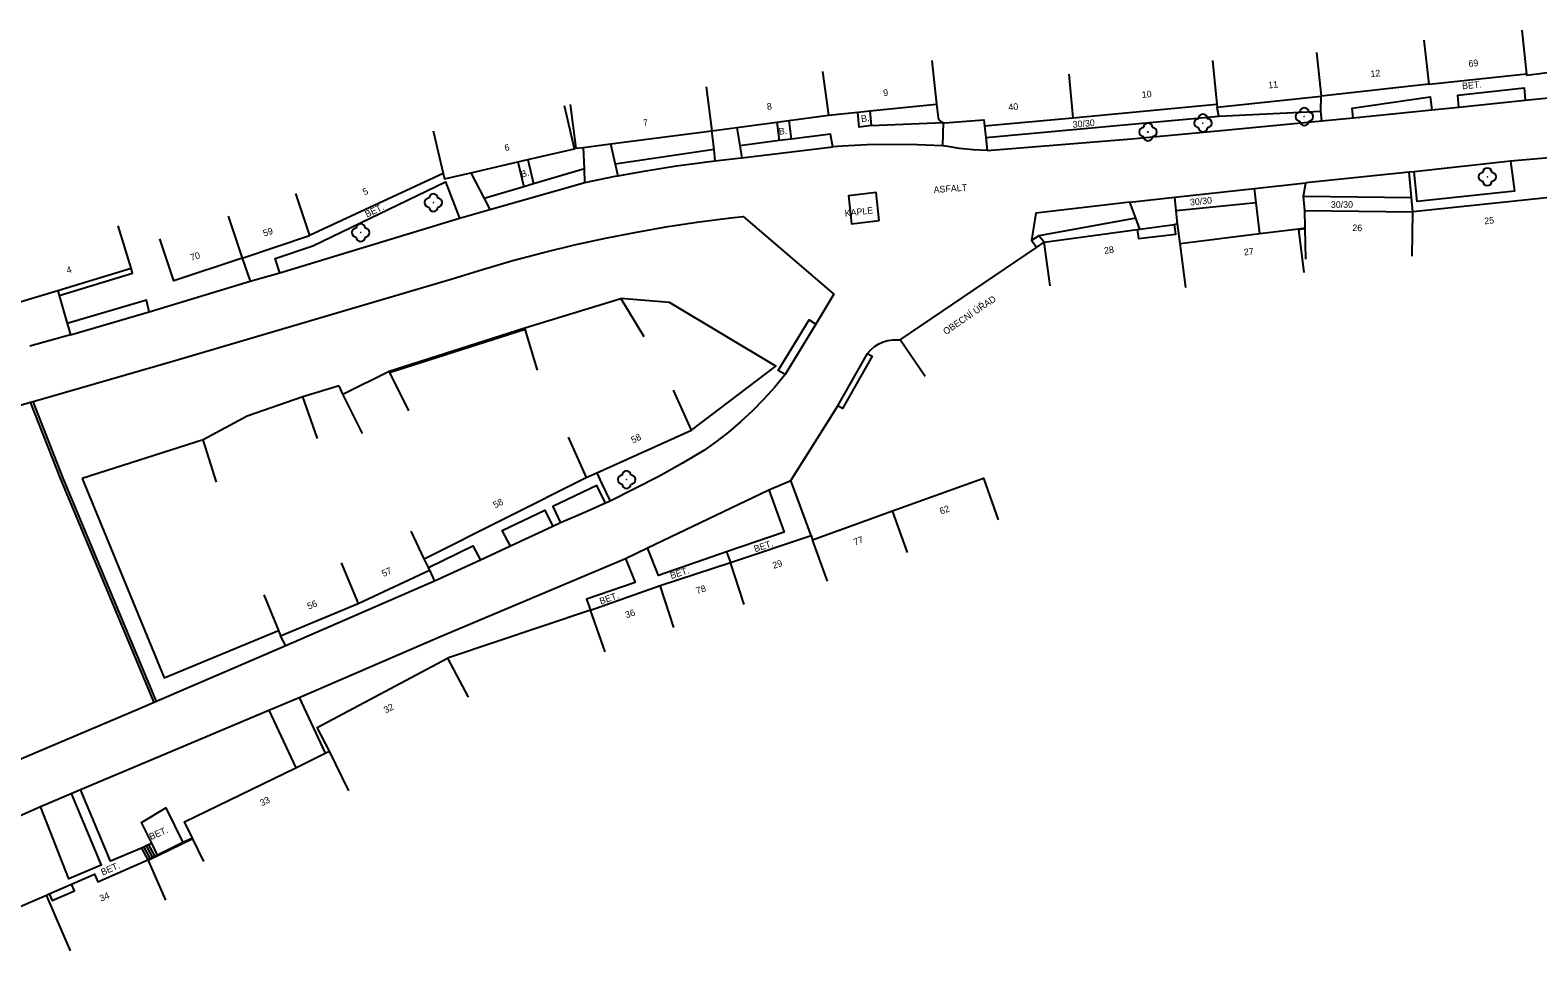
# Model space of a CAD drawing. Extents: x -544674 to -541478, y -1199076 to -1195527.
# Drawn here: x -544563.4 to -544392.6, y -1198429.7 to -1198325.4 of the extents above; entities that cross this region are included whole.
import ezdxf

# ---------------------------------------------------------------- set-up
doc = ezdxf.new("R2010")
doc.units = 0
for name, color, linetype in [('BUDOVY_MĚŘ', 7, 'Continuous'), ('POMOC_POPIS', 7, 'Continuous'), ('ROZHRANÍ_PLOCH', 7, 'Continuous'), ('ZELEŇ', 7, 'Continuous'), ('ZN_DOPLŇKOVÉ', 7, 'Continuous'), ('Č_POPIS_ORIENT', 7, 'Continuous')]:
    doc.layers.add(name, color=color, linetype=linetype)

msp = doc.modelspace()

# ---------------------------------------------------------------- linework, layer by layer
at = {"layer": 'BUDOVY_MĚŘ'}
for points in [[(-544394.36, -1198325.38), (-544393.83, -1198330.35)], [(-544417.64, -1198327.9), (-544417.11, -1198332.87)], [(-544405.46, -1198326.52), (-544404.9, -1198331.49)], [(-544461.21, -1198328.81), (-544460.71, -1198333.78)], [(-544429.41, -1198328.8), (-544428.94, -1198333.77)], [(-544382.75, -1198329.1), (-544393.81, -1198330.5), (-544393.83, -1198330.35)], [(-544473.6, -1198330.05), (-544472.93, -1198335)], [(-544445.68, -1198330.35), (-544445.23, -1198335.33)], [(-544393.83, -1198330.35), (-544404.89, -1198331.54), (-544404.9, -1198331.49)], [(-544486.8, -1198331.82), (-544486.16, -1198336.78)], [(-544428.9, -1198334.12), (-544417.11, -1198332.87)], [(-544404.9, -1198331.49), (-544417.11, -1198332.87)], [(-544506.99, -1198340.04), (-544501.71, -1198338.83), (-544502.83, -1198333.96)], [(-544502.18, -1198333.81), (-544501.54, -1198338.77), (-544500.68, -1198338.66)], [(-544472.93, -1198335), (-544469.61, -1198334.67)], [(-544469.61, -1198334.67), (-544468.26, -1198334.53)], [(-544468.26, -1198334.53), (-544460.71, -1198333.78)], [(-544460.71, -1198333.78), (-544460.51, -1198335.26), (-544460.49, -1198335.36), (-544460.38, -1198335.58), (-544460.21, -1198335.74), (-544459.94, -1198335.86)], [(-544445.23, -1198335.33), (-544428.94, -1198333.77)], [(-544428.94, -1198333.77), (-544428.9, -1198334.12)], [(-544486.16, -1198336.78), (-544483.3, -1198336.4)], [(-544483.3, -1198336.4), (-544478.79, -1198335.79)], [(-544478.79, -1198335.79), (-544477.43, -1198335.61)], [(-544477.43, -1198335.61), (-544472.93, -1198335)], [(-544459.94, -1198335.86), (-544459.76, -1198335.87), (-544455.32, -1198335.54), (-544455.26, -1198336.24)], [(-544455.26, -1198336.24), (-544445.23, -1198335.33)], [(-544517.71, -1198336.77), (-544516.57, -1198341.64)], [(-544497.61, -1198338.26), (-544486.16, -1198336.78)], [(-544500.68, -1198338.66), (-544497.61, -1198338.26)], [(-544516.57, -1198341.64), (-544516.43, -1198342.22), (-544513.46, -1198341.53)], [(-544513.46, -1198341.53), (-544508.11, -1198340.3)], [(-544508.11, -1198340.3), (-544506.99, -1198340.04)], [(-544516.57, -1198341.64), (-544531.73, -1198348.64)], [(-544533.32, -1198343.9), (-544531.73, -1198348.64)], [(-544467.2, -1198346.93), (-544467.53, -1198343.78), (-544470.66, -1198344.17), (-544470.33, -1198347.32), (-544467.2, -1198346.93)], [(-544390.48, -1198344.28), (-544406.74, -1198345.98)], [(-544540.93, -1198346.46), (-544539.35, -1198351.2)], [(-544418.95, -1198345.83), (-544406.74, -1198345.98)], [(-544418.92, -1198347.76), (-544418.95, -1198345.83)], [(-544406.8, -1198350.98), (-544406.74, -1198345.98)], [(-544551.94, -1198352.36), (-544553.39, -1198347.57)], [(-544448.51, -1198349.41), (-544437.94, -1198347.96)], [(-544437.94, -1198347.96), (-544437.79, -1198349), (-544433.57, -1198348.5), (-544433.73, -1198347.39)], [(-544437.94, -1198347.96), (-544437.66, -1198347.92)], [(-544437.66, -1198347.92), (-544433.73, -1198347.39)], [(-544433.38, -1198347.34), (-544433.73, -1198347.39)], [(-544433.07, -1198349.57), (-544433.38, -1198347.34)], [(-544424.07, -1198348.43), (-544419.69, -1198347.88)], [(-544419.69, -1198347.88), (-544419.68, -1198347.98)], [(-544419.68, -1198347.98), (-544419.06, -1198352.84)], [(-544418.92, -1198347.86), (-544418.92, -1198347.76)], [(-544418.86, -1198351.33), (-544418.92, -1198347.86)], [(-544539.35, -1198351.2), (-544547.09, -1198353.78), (-544548.67, -1198349.04)], [(-544539.35, -1198351.2), (-544531.73, -1198348.64)], [(-544464.79, -1198360.48), (-544449.38, -1198350)], [(-544449.38, -1198350), (-544448.51, -1198349.41)], [(-544447.83, -1198354.36), (-544448.51, -1198349.41)], [(-544433.07, -1198349.57), (-544424.07, -1198348.43)], [(-544432.45, -1198354.53), (-544433.07, -1198349.57)], [(-544560.26, -1198354.88), (-544551.94, -1198352.36)], [(-544564.79, -1198356.25), (-544560.26, -1198354.88)], [(-544507.35, -1198359.11), (-544496.46, -1198355.77)], [(-544496.46, -1198355.77), (-544493.85, -1198360.1)], [(-544507.31, -1198359.25), (-544507.35, -1198359.11)], [(-544505.88, -1198363.89), (-544507.31, -1198359.25)], [(-544461.98, -1198364.62), (-544464.79, -1198360.48)], [(-544527.94, -1198366.61), (-544522.72, -1198364.03)], [(-544522.72, -1198364.03), (-544522.65, -1198364.17)], [(-544522.65, -1198364.17), (-544520.51, -1198368.51)], [(-544525.73, -1198371.09), (-544527.94, -1198366.61)], [(-544488.44, -1198370.72), (-544490.49, -1198366.16)], [(-544502.43, -1198371.51), (-544500.38, -1198376.07)], [(-544499.17, -1198375.53), (-544488.44, -1198370.72)], [(-544500.38, -1198376.07), (-544499.17, -1198375.53)], [(-544518.73, -1198385.28), (-544500.38, -1198376.07)], [(-544465.66, -1198379.84), (-544455.38, -1198376.14), (-544453.69, -1198380.85)], [(-544474.74, -1198383.12), (-544465.66, -1198379.84)], [(-544463.97, -1198384.55), (-544465.66, -1198379.84)], [(-544518.73, -1198385.28), (-544520.23, -1198382.16)], [(-544484.05, -1198385.69), (-544474.9, -1198382.65)], [(-544474.9, -1198382.65), (-544474.74, -1198383.12)], [(-544473.04, -1198387.83), (-544474.74, -1198383.12)], [(-544528.13, -1198385.74), (-544526.22, -1198390.36)], [(-544518.26, -1198386.26), (-544518.73, -1198385.28)], [(-544492.01, -1198388.3), (-544484.05, -1198385.69)], [(-544482.47, -1198390.44), (-544484.05, -1198385.69)], [(-544526.22, -1198390.36), (-544518.12, -1198386.55)], [(-544518.12, -1198386.55), (-544518.26, -1198386.26)], [(-544536.92, -1198389.37), (-544535.25, -1198393.42)], [(-544499.91, -1198391.1), (-544492.01, -1198388.3)], [(-544490.45, -1198393.05), (-544492.01, -1198388.3)], [(-544535.01, -1198393.99), (-544526.22, -1198390.36)], [(-544498.24, -1198395.81), (-544499.91, -1198391.1)], [(-544535.25, -1198393.42), (-544535.01, -1198393.99)], [(-544529.47, -1198407.09), (-544530.85, -1198404.38), (-544516.09, -1198396.55)], [(-544516.09, -1198396.55), (-544513.75, -1198400.97)], [(-544533.29, -1198408.95), (-544529.94, -1198407.32)], [(-544529.94, -1198407.32), (-544529.47, -1198407.09)], [(-544527.28, -1198411.58), (-544529.47, -1198407.09)], [(-544545, -1198416.92), (-544545.89, -1198415.1), (-544533.29, -1198408.95)], [(-544544.96, -1198417.01), (-544545, -1198416.92)], [(-544543.7, -1198419.59), (-544544.96, -1198417.01)], [(-544558.68, -1198422.15), (-544556.1, -1198421.02), (-544555.73, -1198421.87), (-544550.06, -1198419.39)], [(-544550.06, -1198419.39), (-544550.02, -1198419.48)], [(-544550.02, -1198419.48), (-544548.05, -1198423.97)], [(-544566.1, -1198425.35), (-544561.51, -1198423.39)], [(-544561.51, -1198423.39), (-544561.21, -1198423.25)], [(-544558.81, -1198429.7), (-544561.51, -1198423.39)], [(-544561.21, -1198423.25), (-544558.68, -1198422.15)], [(-544561.21, -1198423.25), (-544560.88, -1198424.01), (-544558.35, -1198422.91), (-544558.68, -1198422.15)]]:
    msp.add_lwpolyline(points, dxfattribs=at)
at = {"layer": 'ROZHRANÍ_PLOCH'}
for points in [[(-544417.16, -1198334.55), (-544417.11, -1198332.87)], [(-544413.47, -1198335.32), (-544413.58, -1198334.21), (-544404.76, -1198332.92), (-544404.56, -1198334.4)], [(-544401.5, -1198334.09), (-544401.64, -1198332.75), (-544394.11, -1198331.92), (-544394, -1198333.33)], [(-544394, -1198333.33), (-544389.48, -1198332.87)], [(-544468.1, -1198336.17), (-544469.44, -1198336.37), (-544469.61, -1198334.67)], [(-544468.26, -1198334.53), (-544468.1, -1198336.17)], [(-544428.72, -1198335.14), (-544428.9, -1198334.12)], [(-544428.72, -1198335.14), (-544417.16, -1198334.55)], [(-544417.05, -1198335.66), (-544417.16, -1198334.55)], [(-544413.47, -1198335.32), (-544404.56, -1198334.4)], [(-544404.56, -1198334.4), (-544401.5, -1198334.09)], [(-544401.5, -1198334.09), (-544394, -1198333.33)], [(-544483.3, -1198336.4), (-544482.96, -1198338.48)], [(-544478.79, -1198335.79), (-544478.51, -1198337.9)], [(-544477.43, -1198335.61), (-544477.15, -1198337.72)], [(-544459.94, -1198335.86), (-544460.02, -1198338.47)], [(-544455.26, -1198336.24), (-544455.12, -1198337.56)], [(-544455.12, -1198337.56), (-544428.72, -1198335.14)], [(-544454.97, -1198339.01), (-544438.61, -1198337.71), (-544428.83, -1198336.8), (-544417.05, -1198335.66)], [(-544417.05, -1198335.66), (-544413.47, -1198335.32)], [(-544485.9, -1198338.92), (-544486.16, -1198336.78)], [(-544478.51, -1198337.9), (-544482.96, -1198338.48)], [(-544477.15, -1198337.72), (-544478.51, -1198337.9)], [(-544472.43, -1198338.59), (-544472.7, -1198337.15), (-544477.15, -1198337.72)], [(-544455.12, -1198337.56), (-544454.97, -1198339.01)], [(-544500.58, -1198341.11), (-544500.68, -1198338.66)], [(-544497.61, -1198338.26), (-544497.08, -1198340.58)], [(-544485.9, -1198338.92), (-544497.08, -1198340.58)], [(-544485.75, -1198340.19), (-544485.9, -1198338.92)], [(-544485.75, -1198340.19), (-544483.18, -1198339.9), (-544482.73, -1198339.86)], [(-544482.96, -1198338.48), (-544482.73, -1198339.86)], [(-544482.73, -1198339.86), (-544472.43, -1198338.59)], [(-544460.02, -1198338.47), (-544462.86, -1198338.36), (-544465.7, -1198338.34), (-544468.54, -1198338.39), (-544471.38, -1198338.52), (-544472.43, -1198338.59)], [(-544454.97, -1198339.01), (-544456.53, -1198338.93), (-544458.08, -1198338.78), (-544459.62, -1198338.54), (-544460.02, -1198338.47)], [(-544391.29, -1198339.85), (-544395.67, -1198340.21)], [(-544513.46, -1198341.53), (-544511.95, -1198344.46)], [(-544508.11, -1198340.3), (-544507.46, -1198343.13)], [(-544506.99, -1198340.04), (-544506.35, -1198342.81)], [(-544500.58, -1198341.11), (-544506.35, -1198342.81)], [(-544500.52, -1198342.64), (-544500.58, -1198341.11)], [(-544497.08, -1198340.58), (-544496.78, -1198341.89)], [(-544496.78, -1198341.89), (-544493.62, -1198341.31), (-544490.15, -1198340.76), (-544486.67, -1198340.29), (-544485.75, -1198340.19)], [(-544407.13, -1198341.48), (-544418.84, -1198342.68)], [(-544406.58, -1198341.42), (-544407.13, -1198341.48)], [(-544406.87, -1198344.35), (-544407.13, -1198341.48)], [(-544395.67, -1198340.21), (-544406.58, -1198341.42)], [(-544395.67, -1198340.21), (-544395.21, -1198343.63), (-544406.24, -1198344.81), (-544406.58, -1198341.42)], [(-544535.11, -1198352.87), (-544535.61, -1198351.26), (-544531.36, -1198349.81), (-544516.32, -1198342.56), (-544514.74, -1198346.69)], [(-544507.46, -1198343.13), (-544511.95, -1198344.46)], [(-544511.31, -1198345.71), (-544500.52, -1198342.64)], [(-544506.35, -1198342.81), (-544507.46, -1198343.13)], [(-544500.52, -1198342.64), (-544497.08, -1198341.94), (-544496.78, -1198341.89)], [(-544424.67, -1198343.32), (-544418.84, -1198342.68)], [(-544419.11, -1198344.2), (-544418.84, -1198342.68)], [(-544511.95, -1198344.46), (-544511.31, -1198345.71)], [(-544438.77, -1198344.88), (-544449.44, -1198346.12), (-544449.91, -1198349.23)], [(-544438.77, -1198344.88), (-544433.7, -1198344.32)], [(-544438.11, -1198346.68), (-544438.77, -1198344.88)], [(-544433.7, -1198344.32), (-544424.67, -1198343.32)], [(-544433.54, -1198345.87), (-544433.7, -1198344.32)], [(-544424.48, -1198344.94), (-544433.54, -1198345.87)], [(-544424.48, -1198344.94), (-544424.67, -1198343.32)], [(-544424.07, -1198348.43), (-544424.48, -1198344.94)], [(-544419.11, -1198344.2), (-544406.87, -1198344.35)], [(-544418.95, -1198345.83), (-544419.11, -1198344.2)], [(-544406.74, -1198345.98), (-544406.87, -1198344.35)], [(-544563.04, -1198367.46), (-544547.23, -1198362.88), (-544515.56, -1198353.57), (-544512.13, -1198352.49), (-544508.68, -1198351.49), (-544505.2, -1198350.56), (-544501.71, -1198349.72), (-544498.2, -1198348.95), (-544494.67, -1198348.26), (-544491.13, -1198347.64), (-544487.57, -1198347.11), (-544484.01, -1198346.66), (-544482.61, -1198346.5), (-544472.32, -1198355.31), (-544474.36, -1198358.68)], [(-544535.11, -1198352.87), (-544514.74, -1198346.69)], [(-544514.74, -1198346.69), (-544511.31, -1198345.71)], [(-544438.11, -1198346.68), (-544449.1, -1198348.7)], [(-544437.66, -1198347.92), (-544438.11, -1198346.68)], [(-544433.38, -1198347.34), (-544433.54, -1198345.87)], [(-544419.69, -1198347.88), (-544418.92, -1198347.76)], [(-544419.68, -1198347.98), (-544418.92, -1198347.86)], [(-544449.1, -1198348.7), (-544449.91, -1198349.23)], [(-544449.38, -1198350), (-544449.91, -1198349.23)], [(-544448.51, -1198349.41), (-544449.1, -1198348.7)], [(-544539.35, -1198351.2), (-544538.44, -1198353.84)], [(-544560.09, -1198355.45), (-544551.77, -1198352.93), (-544551.94, -1198352.36)], [(-544538.44, -1198353.84), (-544535.11, -1198352.87)], [(-544560.26, -1198354.88), (-544560.09, -1198355.45)], [(-544549.9, -1198357.28), (-544538.44, -1198353.84)], [(-544560.09, -1198355.45), (-544559.17, -1198358.61)], [(-544549.9, -1198357.28), (-544550.19, -1198355.99), (-544559.17, -1198358.61)], [(-544559.17, -1198358.61), (-544558.79, -1198359.9)], [(-544558.79, -1198359.9), (-544549.9, -1198357.28)], [(-544558.79, -1198359.9), (-544563.43, -1198361.19)], [(-544522.72, -1198364.03), (-544507.35, -1198359.11)], [(-544522.65, -1198364.17), (-544507.31, -1198359.25)], [(-544468.5, -1198362.01), (-544468.14, -1198361.59), (-544467.71, -1198361.22), (-544467.24, -1198360.92), (-544466.73, -1198360.69), (-544466.2, -1198360.53), (-544465.65, -1198360.45), (-544465.09, -1198360.45), (-544464.79, -1198360.48)], [(-544477.85, -1198364.41), (-544479.02, -1198365.83), (-544480.25, -1198367.19), (-544481.54, -1198368.5), (-544482.89, -1198369.75), (-544484.29, -1198370.95), (-544485.74, -1198372.08), (-544487.06, -1198373.02), (-544489.48, -1198374.45), (-544492.17, -1198375.94), (-544494.9, -1198377.37), (-544497.67, -1198378.73)], [(-544527.94, -1198366.61), (-544528.37, -1198365.68)], [(-544572.34, -1198370.15), (-544563.33, -1198367.54)], [(-544563.33, -1198367.54), (-544563.04, -1198367.46)], [(-544477.2, -1198376.42), (-544471.87, -1198367.95)], [(-544499.17, -1198375.53), (-544498.65, -1198376.7), (-544497.67, -1198378.73)], [(-544498.21, -1198378.97), (-544499.19, -1198376.96), (-544504.17, -1198379.35), (-544503.28, -1198381.21)], [(-544493.42, -1198384.05), (-544479.68, -1198377.45)], [(-544479.68, -1198377.45), (-544477.95, -1198382.25), (-544484.48, -1198384.49)], [(-544479.68, -1198377.45), (-544477.2, -1198376.42)], [(-544474.9, -1198382.65), (-544477.2, -1198376.42)], [(-544498.21, -1198378.97), (-544500.45, -1198380), (-544503.28, -1198381.21)], [(-544497.67, -1198378.73), (-544498.21, -1198378.97)], [(-544508.94, -1198383.84), (-544509.89, -1198382.09), (-544505.05, -1198379.77), (-544504.16, -1198381.62)], [(-544504.16, -1198381.62), (-544508.94, -1198383.84)], [(-544503.28, -1198381.21), (-544504.16, -1198381.62)], [(-544518.26, -1198386.26), (-544513.24, -1198383.81), (-544512.37, -1198385.42)], [(-544508.94, -1198383.84), (-544512.37, -1198385.42)], [(-544495.92, -1198385.25), (-544493.42, -1198384.05)], [(-544484.48, -1198384.49), (-544492.19, -1198387.16), (-544493.42, -1198384.05)], [(-544532.9, -1198400.98), (-544517.09, -1198394.16), (-544495.92, -1198385.25)], [(-544512.37, -1198385.42), (-544517.56, -1198387.82)], [(-544495.92, -1198385.25), (-544494.85, -1198387.97), (-544500.34, -1198389.87), (-544499.91, -1198391.1)], [(-544484.48, -1198384.49), (-544484.05, -1198385.69)], [(-544518.12, -1198386.55), (-544517.56, -1198387.82)], [(-544517.56, -1198387.82), (-544534.4, -1198395.13)], [(-544534.4, -1198395.13), (-544535.01, -1198393.99)], [(-544534.4, -1198395.13), (-544548.98, -1198401.42), (-544549.06, -1198401.45)], [(-544536.33, -1198402.43), (-544532.9, -1198400.98)], [(-544532.9, -1198400.98), (-544529.94, -1198407.32)], [(-544549.34, -1198401.57), (-544551, -1198402.28), (-544575.6, -1198412.69), (-544581.92, -1198415.32)], [(-544557.66, -1198411.42), (-544548.89, -1198407.73), (-544536.33, -1198402.43)], [(-544549.06, -1198401.45), (-544549.34, -1198401.57)], [(-544536.33, -1198402.43), (-544533.29, -1198408.95)], [(-544558.73, -1198411.87), (-544557.66, -1198411.42)], [(-544550.77, -1198418.07), (-544554.27, -1198419.54), (-544557.66, -1198411.42)], [(-544569.8, -1198416.69), (-544562.19, -1198413.33)], [(-544562.19, -1198413.33), (-544558.73, -1198411.87)], [(-544558.73, -1198411.87), (-544555.34, -1198420), (-544559, -1198421.53), (-544562.19, -1198413.33)], [(-544549.61, -1198417.51), (-544550.77, -1198415.14), (-544548, -1198413.48), (-544546.07, -1198417.44)], [(-544550.5, -1198417.94), (-544550.77, -1198418.07)], [(-544550.77, -1198418.07), (-544550.06, -1198419.39)], [(-544550.23, -1198417.81), (-544550.5, -1198417.94)], [(-544550.5, -1198417.94), (-544549.79, -1198419.26)], [(-544549.96, -1198417.68), (-544550.23, -1198417.81)], [(-544550.23, -1198417.81), (-544549.52, -1198419.13)], [(-544549.61, -1198417.51), (-544549.96, -1198417.68)], [(-544549.96, -1198417.68), (-544549.25, -1198419)], [(-544548.96, -1198418.86), (-544549.61, -1198417.51)]]:
    msp.add_lwpolyline(points, dxfattribs=at)
at = {"layer": 'ZELEŇ'}
for centre in [(-544430.5, -1198335.91), (-544419.02, -1198335.18), (-544436.73, -1198336.92), (-544398.28, -1198342), (-544517.69, -1198344.92), (-544525.93, -1198348.32), (-544495.81, -1198376.31)]:
    msp.add_circle(centre, 0.0005, dxfattribs=at)
for centre, start, end in [((-544419.52, -1198335.18), 89.99999, 269.99999), ((-544419.02, -1198334.68), 0, 179.99999), ((-544418.52, -1198335.18), 270, 89.99999), ((-544437.23, -1198336.92), 89.99999, 269.99999), ((-544436.73, -1198336.42), 0, 179.99999), ((-544436.23, -1198336.92), 270, 89.99999), ((-544431, -1198335.91), 89.99999, 269.99999), ((-544430.5, -1198335.41), 0, 179.99999), ((-544430.5, -1198336.41), 179.99999, 359.99999), ((-544430, -1198335.91), 270, 89.99999), ((-544419.02, -1198335.68), 179.99999, 359.99999), ((-544436.73, -1198337.42), 179.99999, 359.99999), ((-544398.78, -1198342), 89.99999, 269.99999), ((-544398.28, -1198341.5), 0, 179.99999), ((-544397.78, -1198342), 270, 89.99999), ((-544398.28, -1198342.5), 179.99999, 359.99999), ((-544518.19, -1198344.92), 89.99999, 269.99999), ((-544517.69, -1198344.42), 0, 179.99999), ((-544517.19, -1198344.92), 270, 89.99999), ((-544517.69, -1198345.42), 179.99999, 359.99999), ((-544526.43, -1198348.32), 89.99999, 269.99999), ((-544525.93, -1198347.82), 0, 179.99999), ((-544525.43, -1198348.32), 270, 89.99999), ((-544525.93, -1198348.82), 179.99999, 359.99999), ((-544495.81, -1198375.81), 0, 179.99999), ((-544496.31, -1198376.31), 89.99999, 269.99999), ((-544495.81, -1198376.81), 179.99999, 359.99999), ((-544495.31, -1198376.31), 270, 89.99999)]:
    msp.add_arc(centre, 0.5, start, end, dxfattribs=at)
at = {"layer": 'ZN_DOPLŇKOVÉ'}
for points in [[(-544468.1, -1198336.17), (-544459.94, -1198335.86)], [(-544488.44, -1198370.72), (-544478.91, -1198363.45), (-544490.93, -1198356.23), (-544496.46, -1198355.77)], [(-544477.85, -1198364.41), (-544478.62, -1198363.94), (-544475.13, -1198358.21), (-544474.36, -1198358.68)], [(-544474.36, -1198358.68), (-544477.85, -1198364.41)], [(-544471.87, -1198367.95), (-544468.5, -1198362.01)], [(-544468.5, -1198362.01), (-544467.98, -1198362.31), (-544471.35, -1198368.25), (-544471.87, -1198367.95)], [(-544532.49, -1198366.91), (-544538.8, -1198369.13), (-544543.78, -1198371.81)], [(-544528.37, -1198365.68), (-544532.49, -1198366.91)], [(-544530.83, -1198371.63), (-544532.49, -1198366.91)], [(-544549.34, -1198401.57), (-544559.92, -1198376.26), (-544563.33, -1198367.54)], [(-544549.06, -1198401.45), (-544559.64, -1198376.15), (-544563.04, -1198367.46)], [(-544543.78, -1198371.81), (-544557.48, -1198376.17)], [(-544542.26, -1198376.58), (-544543.78, -1198371.81)], [(-544557.48, -1198376.17), (-544548.18, -1198398.76), (-544535.25, -1198393.42)], [(-544499.91, -1198391.1), (-544516.09, -1198396.55)], [(-544544.96, -1198417.01), (-544550.02, -1198419.48)], [(-544546.07, -1198417.44), (-544548.96, -1198418.86)], [(-544545, -1198416.92), (-544546.07, -1198417.44)], [(-544549.79, -1198419.26), (-544550.06, -1198419.39)], [(-544549.52, -1198419.13), (-544549.79, -1198419.26)], [(-544549.25, -1198419), (-544549.52, -1198419.13)], [(-544548.96, -1198418.86), (-544549.25, -1198419)]]:
    msp.add_lwpolyline(points, dxfattribs=at)

# ---------------------------------------------------------------- texts
at = {"layer": 'POMOC_POPIS'}
for s, rotation, p in [('BET.', 5.21999, (-544401.11, -1198332.09)), ('B.', 7.35999, (-544478.51, -1198337.24)), ('B.', 7.35999, (-544469.19, -1198335.8)), ('30/30', 5.23999, (-544445.23, -1198336.45)), ('B.', 16.08, (-544507.68, -1198342.1)), ('ASFALT', 4.16002, (-544460.99, -1198343.84)), ('30/30', 5.23999, (-544431.95, -1198345.25)), ('30/30', 0.31003, (-544416.01, -1198345.52)), ('BET.', 25.74001, (-544525.22, -1198346.63)), ('KAPLE', 7.09998, (-544471.04, -1198346.53)), ('OBECNÍ ÚŘAD', 34.20999, (-544459.63, -1198359.93)), ('BET.', 18.38003, (-544481.23, -1198384.54)), ('BET.', 18.14999, (-544490.73, -1198387.58)), ('BET.', 19.51998, (-544498.71, -1198390.47)), ('BET.', 23.45999, (-544549.7, -1198417.16)), ('BET.', 23.45999, (-544555.17, -1198421.18))]:
    msp.add_text(s, height=0.75, rotation=rotation, dxfattribs=at).set_placement(p)
at = {"layer": 'Č_POPIS_ORIENT'}
for s, rotation, p in [('69', 6.13999, (-544400.38, -1198329.55)), ('11', 6.04998, (-544423.07, -1198331.99)), ('12', 6.45002, (-544411.48, -1198330.72)), ('9', 5.70001, (-544466.7, -1198332.87)), ('10', 5.46, (-544437.4, -1198333.07)), ('8', 7.65999, (-544479.86, -1198334.42)), ('40', 5.18, (-544452.51, -1198334.48)), ('7', 7.37001, (-544493.9, -1198336.27)), ('6', 12.96999, (-544509.55, -1198339.1)), ('5', 24.78999, (-544525.5, -1198344.11)), ('25', 5.96999, (-544398.6, -1198347.39)), ('59', 18.57002, (-544536.85, -1198348.78)), ('26', 359.3, (-544413.58, -1198348.15)), ('28', 7.78999, (-544441.66, -1198350.74)), ('27', 7.18999, (-544425.82, -1198350.92)), ('70', 18.42999, (-544545.11, -1198351.54)), ('4', 16.83, (-544559.14, -1198352.97)), ('58', 26.64999, (-544495.07, -1198372.22)), ('58', 26.64999, (-544510.69, -1198379.57)), ('62', 19.79002, (-544460.18, -1198380.26)), ('77', 19.87997, (-544469.95, -1198383.78)), ('29', 18.38003, (-544479.14, -1198386.43)), ('57', 25.18997, (-544523.34, -1198387.35)), ('78', 18.14999, (-544487.8, -1198389.29)), ('56', 22.44001, (-544531.8, -1198391.04)), ('36', 19.51998, (-544495.81, -1198392.03)), ('32', 27.95003, (-544523.08, -1198402.81)), ('33', 26.00002, (-544537.13, -1198413.33)), ('34', 23.64998, (-544555.33, -1198424.15))]:
    msp.add_text(s, height=0.75, rotation=rotation, dxfattribs=at).set_placement(p)

doc.saveas('drawing.dxf')
